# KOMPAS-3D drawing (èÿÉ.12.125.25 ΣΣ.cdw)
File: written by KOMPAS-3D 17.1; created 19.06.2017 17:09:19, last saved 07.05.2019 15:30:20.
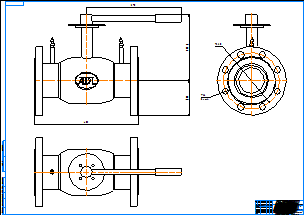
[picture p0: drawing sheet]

Sheet 1: A0, landscape

Title block, sheet 1: name: КШР.12.125.25 фф; material: Внимание! Данный продукт является объектом авторского права ООО «Торговый Дом АДЛ». / Запрещается изменение, копирование, распространение / (в том числе путем копирования на другие сайты и ресурсы в Интернете) / или любое иное использование информации и объектов без предварительного / согласия правообладателя (ООО «Торговый Дом АДЛ»).; scale: 1:1; sheets: 1; organisation: ООО "Торговый дом АДЛ"; sheet format: A0; stored path: C:\Users\tra\Desktop\2д чертежи\Шаровые краны БИВАЛ\КШР_Бивал_серия_12\KOMPAS 2D\КШР.12.125.25 фф.cdw

Views: Спереди 1, Проекционный вид 2, Проекционный вид 3
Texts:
  Klimkovich
  ADL
Dimensions and other numbers on the sheet: 405; 370; 258,4; 135; 220; 26; 8 отв.; 1:1; 1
